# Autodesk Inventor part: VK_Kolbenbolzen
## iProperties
Author: Ulrich
Created: 2003-12
Part Number: VK_Kolbenbolzen
Material: Stahl (hohe Festigk., niedr. Legier.)
Document SubType Name: Modellieren
Designer: Ulrich
Control State: 0
Master: False
Checked Out: False
PropertySet Name: Design Tracking Control
Shininess: 20.0
Angle Display Precision: 2
Document Length Units: 11269
Document Angle Units: 11283
Document Time Units: 11279
Document Mass Units: 11290
Document Length Units Precision: 3
Document Angle Units Precision: 2
Compacted: True
PropertySet Name: _Private Model Information
Density: 0.0
Volumn: 0.0
Area: 0.0
PropertySet Name: Model Information
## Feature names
1. Drehung1 [Revolution]
